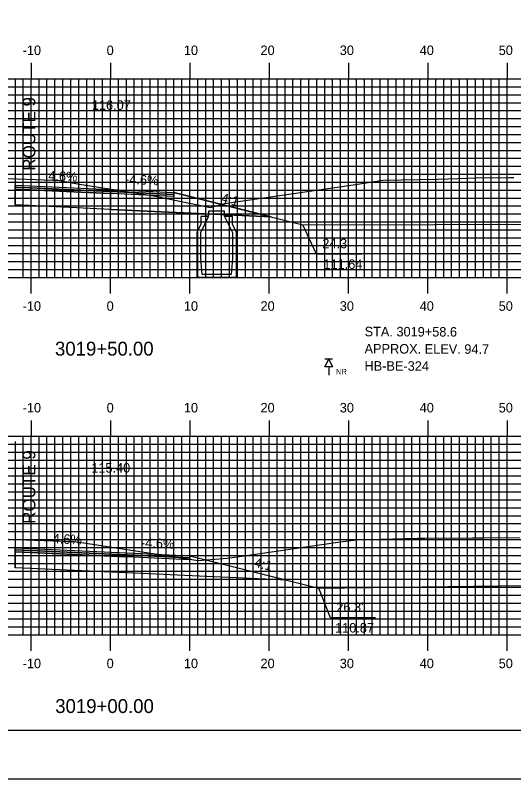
# Model space of a CAD drawing. Extents: x 1685979 to 1686323, y 461260 to 461480.
# Drawn here: x 1686133.3 to 1686196.1, y 461260 to 461356.1 of the extents above; entities that cross this region are included whole.
import ezdxf

# ---------------------------------------------------------------- set-up
doc = ezdxf.new("R2010")
doc.units = 0
for name, color, linetype in [('ANNOTATION', 7, 'Continuous'), ('BORDER', 7, 'Continuous'), ('BORING - NO REFUSAL', 7, 'Continuous'), ('D_Roadway_Centerline_Text', 7, 'Continuous'), ('D_Roadway_Edge_Shoulder', 7, 'Continuous'), ('D_Roadway_Edge_TW', 7, 'Continuous'), ('D_Roadway_Pavement', 7, 'Continuous'), ('D_Roadway_SlopeLines', 7, 'Continuous'), ('D_Roadway_SubGrade', 7, 'Continuous'), ('H_V ANNOTATION', 7, 'Continuous'), ('M_Drainage_CB', 7, 'Continuous'), ('M_Roadway_Centerline', 7, 'Continuous'), ('MAJOR', 7, 'Continuous'), ('MINOR', 7, 'Continuous'), ('PLOT BOUNDARY', 7, 'Continuous'), ('S_Roadway_Centerline', 7, 'Continuous')]:
    doc.layers.add(name, color=color, linetype=linetype)

msp = doc.modelspace()

# ---------------------------------------------------------------- linework, layer by layer
at = {"layer": 'ANNOTATION'}
for points in [[(1686176.917, 461326.019), (1686171.226, 461326.019), (1686169.511, 461329.71)], [(1686178.674, 461280.232), (1686172.982, 461280.232), (1686171.511, 461283.946)]]:
    msp.add_lwpolyline(points, dxfattribs=at)
at = {"layer": 'BORDER'}
msp.add_lwpolyline([(1685995.656, 461266.072), (1686315.656, 461266.072), (1686315.656, 461476.072), (1685995.656, 461476.072)], close=True, dxfattribs=at)
at = {"layer": 'BORING - NO REFUSAL'}
for p, q in [((1686173.235, 461312.772), (1686172.276, 461312.772)), ((1686172.756, 461311.813), (1686172.756, 461310.754))]:
    msp.add_line(p, q, dxfattribs=at)
msp.add_lwpolyline([(1686172.756, 461312.772), (1686173.235, 461311.813), (1686172.276, 461311.813)], close=True, dxfattribs=at)
at = {"layer": 'D_Roadway_Edge_Shoulder'}
msp.add_line((1686133.256, 461288.772), (1686133.256, 461289.022), dxfattribs=at)
for points in [[(1686145.256, 461334.141), (1686153.256, 461333.773), (1686153.256, 461333.523), (1686145.256, 461333.891)], [(1686145.256, 461334.141), (1686153.256, 461333.773), (1686153.256, 461333.523), (1686145.256, 461333.891)], [(1686145.256, 461334.141), (1686153.256, 461333.773), (1686153.256, 461333.523), (1686145.256, 461333.891)], [(1686145.256, 461333.891), (1686153.256, 461333.523), (1686153.256, 461333.273), (1686145.256, 461333.641)], [(1686147.256, 461288.378), (1686155.256, 461288.01), (1686155.256, 461287.76), (1686147.256, 461288.128)], [(1686147.256, 461288.128), (1686155.256, 461287.76), (1686155.256, 461287.51), (1686147.256, 461287.878)]]:
    msp.add_lwpolyline(points, close=True, dxfattribs=at)
at = {"layer": 'D_Roadway_Edge_TW'}
for points in [[(1686133.256, 461334.693), (1686145.256, 461334.141), (1686145.256, 461333.891), (1686133.256, 461334.443)], [(1686133.256, 461334.693), (1686145.256, 461334.141), (1686145.256, 461333.891), (1686133.256, 461334.443)], [(1686133.256, 461334.693), (1686145.256, 461334.141), (1686145.256, 461333.891), (1686133.256, 461334.443)], [(1686133.256, 461289.022), (1686147.256, 461288.378), (1686147.256, 461288.128), (1686133.256, 461288.772)], [(1686133.256, 461289.022), (1686147.256, 461288.378), (1686147.256, 461288.128), (1686133.256, 461288.772)]]:
    msp.add_lwpolyline(points, close=True, dxfattribs=at)
for points in [[(1686133.256, 461334.693), (1686133.256, 461334.443)], [(1686145.256, 461333.891), (1686145.256, 461334.141)], [(1686133.256, 461289.022), (1686133.256, 461288.772)], [(1686147.256, 461288.128), (1686147.256, 461288.378)]]:
    msp.add_lwpolyline(points, dxfattribs=at)
at = {"layer": 'D_Roadway_Pavement'}
msp.add_line((1686133.256, 461288.522), (1686133.256, 461288.772), dxfattribs=at)
for points in [[(1686133.256, 461334.443), (1686145.256, 461333.891), (1686145.256, 461333.641), (1686133.256, 461334.193)], [(1686133.256, 461334.443), (1686145.256, 461333.891), (1686145.256, 461333.641), (1686133.256, 461334.193)], [(1686133.256, 461334.443), (1686145.256, 461333.891), (1686145.256, 461333.641), (1686133.256, 461334.193)], [(1686133.256, 461334.443), (1686145.256, 461333.891), (1686145.256, 461333.641), (1686133.256, 461334.193)], [(1686133.256, 461334.443), (1686145.256, 461333.891), (1686145.256, 461333.641), (1686133.256, 461334.193)], [(1686133.256, 461288.772), (1686147.256, 461288.128), (1686147.256, 461287.878), (1686133.256, 461288.522)]]:
    msp.add_lwpolyline(points, close=True, dxfattribs=at)
for points in [[(1686133.256, 461334.443), (1686133.256, 461334.193)], [(1686145.256, 461333.891), (1686145.256, 461333.641)], [(1686145.256, 461333.891), (1686145.256, 461333.641)], [(1686145.256, 461333.891), (1686145.256, 461333.641)], [(1686145.256, 461333.891), (1686145.256, 461333.641)], [(1686145.256, 461333.891), (1686145.256, 461333.641)], [(1686145.256, 461333.891), (1686145.256, 461333.641)], [(1686145.256, 461333.641), (1686145.256, 461333.891)], [(1686145.256, 461333.891), (1686145.256, 461333.641)], [(1686133.256, 461288.772), (1686133.256, 461288.522)], [(1686147.256, 461288.128), (1686147.256, 461287.878)], [(1686147.256, 461288.128), (1686147.256, 461287.878)], [(1686147.256, 461288.128), (1686147.256, 461287.878)], [(1686147.256, 461288.128), (1686147.256, 461287.878)], [(1686147.256, 461288.128), (1686147.256, 461287.878)], [(1686147.256, 461288.128), (1686147.256, 461287.878)], [(1686147.256, 461287.878), (1686147.256, 461288.128)], [(1686147.256, 461288.128), (1686147.256, 461287.878)]]:
    msp.add_lwpolyline(points, dxfattribs=at)
at = {"layer": 'D_Roadway_SlopeLines'}
for points in [[(1686153.256, 461333.773), (1686169.511, 461329.71)], [(1686153.256, 461333.773), (1686169.511, 461329.71)], [(1686153.256, 461333.773), (1686169.511, 461329.71)], [(1686153.256, 461333.773), (1686169.511, 461329.71)], [(1686169.511, 461329.71), (1686252.38, 461329.925)], [(1686169.511, 461329.71), (1686252.38, 461329.925)], [(1686169.511, 461329.71), (1686252.38, 461329.925)], [(1686169.511, 461329.71), (1686252.38, 461329.925)], [(1686155.256, 461288.01), (1686171.511, 461283.946)], [(1686171.511, 461283.946), (1686249.53, 461284.948)], [(1686171.511, 461283.946), (1686249.53, 461284.948)], [(1686171.511, 461283.946), (1686249.53, 461284.948)], [(1686171.511, 461283.946), (1686249.53, 461284.948)]]:
    msp.add_lwpolyline(points, dxfattribs=at)
at = {"layer": 'D_Roadway_SubGrade'}
for p, q in [((1686133.256, 461348.072), (1686133.256, 461332.193)), ((1686133.256, 461302.4), (1686133.256, 461286.522)), ((1686133.256, 461286.522), (1686133.256, 461288.522))]:
    msp.add_line(p, q, dxfattribs=at)
for points in [[(1686133.256, 461334.193), (1686133.256, 461332.193)], [(1686133.256, 461334.193), (1686133.256, 461332.193)], [(1686133.256, 461288.522), (1686133.256, 461286.522)], [(1686133.256, 461288.522), (1686133.256, 461286.522)]]:
    msp.add_lwpolyline(points, dxfattribs=at)
for points in [[(1686133.256, 461334.193), (1686145.256, 461333.641), (1686145.256, 461331.641), (1686133.256, 461332.193)], [(1686133.256, 461334.193), (1686145.256, 461333.641), (1686145.256, 461331.641), (1686133.256, 461332.193)], [(1686133.256, 461334.193), (1686145.256, 461333.641), (1686145.256, 461331.641), (1686133.256, 461332.193)], [(1686145.256, 461331.641), (1686165.511, 461330.71), (1686153.256, 461333.773), (1686153.256, 461333.523), (1686145.256, 461333.891), (1686145.256, 461333.641)], [(1686145.256, 461333.641), (1686145.256, 461333.891), (1686153.256, 461333.523), (1686153.256, 461333.773), (1686165.511, 461330.71), (1686145.256, 461331.641)], [(1686145.256, 461333.641), (1686145.256, 461333.891), (1686153.256, 461333.523), (1686153.256, 461333.773), (1686165.511, 461330.71), (1686145.256, 461331.641)], [(1686145.256, 461331.641), (1686165.511, 461330.71), (1686153.256, 461333.773), (1686153.256, 461333.523), (1686145.256, 461333.891), (1686145.256, 461333.641)], [(1686133.256, 461288.522), (1686147.256, 461287.878), (1686147.256, 461285.878), (1686133.256, 461286.522)], [(1686133.256, 461288.522), (1686147.256, 461287.878), (1686147.256, 461285.878), (1686133.256, 461286.522)], [(1686133.256, 461288.522), (1686147.256, 461287.878), (1686147.256, 461285.878), (1686133.256, 461286.522)], [(1686147.256, 461287.878), (1686147.256, 461288.128), (1686155.256, 461287.76), (1686155.256, 461288.01), (1686167.511, 461284.946), (1686147.256, 461285.878)]]:
    msp.add_lwpolyline(points, close=True, dxfattribs=at)
at = {"layer": 'M_Drainage_CB'}
for p, q in [((1686157.617, 461330.751), (1686156.633, 461330.751)), ((1686156.633, 461330.751), (1686156.633, 461329.766)), ((1686156.633, 461328.749), (1686157.617, 461330.751)), ((1686160.636, 461330.751), (1686159.619, 461330.751)), ((1686159.619, 461330.751), (1686160.636, 461328.749)), ((1686160.636, 461329.766), (1686160.636, 461330.751)), ((1686156.633, 461329.766), (1686156.141, 461328.749)), ((1686161.128, 461328.749), (1686160.636, 461329.766)), ((1686156.141, 461328.749), (1686156.141, 461323.106)), ((1686156.633, 461325.436), (1686156.633, 461328.749)), ((1686160.636, 461328.749), (1686160.636, 461325.436)), ((1686161.128, 461323.106), (1686161.128, 461328.749)), ((1686156.797, 461323.434), (1686156.633, 461325.436)), ((1686160.636, 461325.436), (1686160.472, 461323.434)), ((1686156.141, 461323.106), (1686161.128, 461323.106)), ((1686160.472, 461323.434), (1686156.797, 461323.434))]:
    msp.add_line(p, q, dxfattribs=at)
msp.add_lwpolyline([(1686160.111, 461330.792), (1686159.619, 461330.792), (1686159.619, 461331.416), (1686157.617, 461331.416), (1686157.617, 461330.792), (1686157.125, 461330.792)], dxfattribs=at)
at = {"layer": 'MAJOR'}
for p, q in [((1686135.256, 461350.076), (1686135.256, 461348.072)), ((1686145.256, 461350.076), (1686145.256, 461348.072)), ((1686155.256, 461350.076), (1686155.256, 461348.072)), ((1686165.256, 461350.076), (1686165.256, 461348.072)), ((1686175.256, 461350.076), (1686175.256, 461348.072)), ((1686185.256, 461350.076), (1686185.256, 461348.072)), ((1686195.256, 461350.076), (1686195.256, 461348.072)), ((1686005.256, 461348.072), (1686285.256, 461348.072)), ((1686005.256, 461348.072), (1686285.256, 461348.072)), ((1686135.256, 461323.072), (1686135.256, 461348.072)), ((1686145.256, 461323.072), (1686145.256, 461348.072)), ((1686155.256, 461323.072), (1686155.256, 461348.072)), ((1686165.256, 461323.072), (1686165.256, 461348.072)), ((1686175.256, 461323.072), (1686175.256, 461348.072)), ((1686185.256, 461323.072), (1686185.256, 461348.072)), ((1686195.256, 461323.072), (1686195.256, 461348.072)), ((1686005.256, 461343.072), (1686285.256, 461343.072)), ((1686005.256, 461338.072), (1686285.256, 461338.072)), ((1686005.256, 461333.072), (1686285.256, 461333.072)), ((1686005.256, 461328.072), (1686285.256, 461328.072)), ((1686005.256, 461323.072), (1686285.256, 461323.072)), ((1686005.256, 461323.072), (1686285.256, 461323.072)), ((1686135.256, 461321.068), (1686135.256, 461323.072)), ((1686145.256, 461321.068), (1686145.256, 461323.072)), ((1686155.256, 461321.068), (1686155.256, 461323.072)), ((1686165.256, 461321.068), (1686165.256, 461323.072)), ((1686175.256, 461321.068), (1686175.256, 461323.072)), ((1686185.256, 461321.068), (1686185.256, 461323.072)), ((1686195.256, 461321.068), (1686195.256, 461323.072)), ((1686135.256, 461305.076), (1686135.256, 461303.072)), ((1686145.256, 461305.076), (1686145.256, 461303.072)), ((1686155.256, 461305.076), (1686155.256, 461303.072)), ((1686165.256, 461305.076), (1686165.256, 461303.072)), ((1686175.256, 461305.076), (1686175.256, 461303.072)), ((1686185.256, 461305.076), (1686185.256, 461303.072)), ((1686195.256, 461305.076), (1686195.256, 461303.072)), ((1686005.256, 461303.072), (1686285.256, 461303.072)), ((1686005.256, 461303.072), (1686285.256, 461303.072)), ((1686135.256, 461278.072), (1686135.256, 461303.072)), ((1686145.256, 461278.072), (1686145.256, 461303.072)), ((1686155.256, 461278.072), (1686155.256, 461303.072)), ((1686165.256, 461278.072), (1686165.256, 461303.072)), ((1686175.256, 461278.072), (1686175.256, 461303.072)), ((1686185.256, 461278.072), (1686185.256, 461303.072)), ((1686195.256, 461278.072), (1686195.256, 461303.072)), ((1686005.256, 461298.072), (1686285.256, 461298.072)), ((1686005.256, 461293.072), (1686285.256, 461293.072)), ((1686005.256, 461288.072), (1686285.256, 461288.072)), ((1686005.256, 461283.072), (1686285.256, 461283.072)), ((1686005.256, 461278.072), (1686285.256, 461278.072)), ((1686005.256, 461278.072), (1686285.256, 461278.072)), ((1686135.256, 461276.068), (1686135.256, 461278.072)), ((1686145.256, 461276.068), (1686145.256, 461278.072)), ((1686155.256, 461276.068), (1686155.256, 461278.072)), ((1686165.256, 461276.068), (1686165.256, 461278.072)), ((1686175.256, 461276.068), (1686175.256, 461278.072)), ((1686185.256, 461276.068), (1686185.256, 461278.072)), ((1686195.256, 461276.068), (1686195.256, 461278.072))]:
    msp.add_line(p, q, dxfattribs=at)
at = {"layer": 'MINOR'}
for p, q in [((1686134.256, 461323.072), (1686134.256, 461348.072)), ((1686136.256, 461323.072), (1686136.256, 461348.072)), ((1686137.256, 461323.072), (1686137.256, 461348.072)), ((1686138.256, 461323.072), (1686138.256, 461348.072)), ((1686139.256, 461323.072), (1686139.256, 461348.072)), ((1686140.256, 461323.072), (1686140.256, 461348.072)), ((1686141.256, 461323.072), (1686141.256, 461348.072)), ((1686142.256, 461323.072), (1686142.256, 461348.072)), ((1686143.256, 461323.072), (1686143.256, 461348.072)), ((1686144.256, 461323.072), (1686144.256, 461348.072)), ((1686146.256, 461323.072), (1686146.256, 461348.072)), ((1686147.256, 461323.072), (1686147.256, 461348.072)), ((1686148.256, 461323.072), (1686148.256, 461348.072)), ((1686149.256, 461323.072), (1686149.256, 461348.072)), ((1686150.256, 461323.072), (1686150.256, 461348.072)), ((1686151.256, 461323.072), (1686151.256, 461348.072)), ((1686152.256, 461323.072), (1686152.256, 461348.072)), ((1686153.256, 461323.072), (1686153.256, 461348.072)), ((1686154.256, 461323.072), (1686154.256, 461348.072)), ((1686156.256, 461323.072), (1686156.256, 461348.072)), ((1686157.256, 461323.072), (1686157.256, 461348.072)), ((1686158.256, 461323.072), (1686158.256, 461348.072)), ((1686159.256, 461323.072), (1686159.256, 461348.072)), ((1686160.256, 461323.072), (1686160.256, 461348.072)), ((1686161.256, 461323.072), (1686161.256, 461348.072)), ((1686162.256, 461323.072), (1686162.256, 461348.072)), ((1686163.256, 461323.072), (1686163.256, 461348.072)), ((1686164.256, 461323.072), (1686164.256, 461348.072)), ((1686166.256, 461323.072), (1686166.256, 461348.072)), ((1686167.256, 461323.072), (1686167.256, 461348.072)), ((1686168.256, 461323.072), (1686168.256, 461348.072)), ((1686169.256, 461323.072), (1686169.256, 461348.072)), ((1686170.256, 461323.072), (1686170.256, 461348.072)), ((1686171.256, 461323.072), (1686171.256, 461348.072)), ((1686172.256, 461323.072), (1686172.256, 461348.072)), ((1686173.256, 461323.072), (1686173.256, 461348.072)), ((1686174.256, 461323.072), (1686174.256, 461348.072)), ((1686176.256, 461323.072), (1686176.256, 461348.072)), ((1686177.256, 461323.072), (1686177.256, 461348.072)), ((1686178.256, 461323.072), (1686178.256, 461348.072)), ((1686179.256, 461323.072), (1686179.256, 461348.072)), ((1686180.256, 461323.072), (1686180.256, 461348.072)), ((1686181.256, 461323.072), (1686181.256, 461348.072)), ((1686182.256, 461323.072), (1686182.256, 461348.072)), ((1686183.256, 461323.072), (1686183.256, 461348.072)), ((1686184.256, 461323.072), (1686184.256, 461348.072)), ((1686186.256, 461323.072), (1686186.256, 461348.072)), ((1686187.256, 461323.072), (1686187.256, 461348.072)), ((1686188.256, 461323.072), (1686188.256, 461348.072)), ((1686189.256, 461323.072), (1686189.256, 461348.072)), ((1686190.256, 461323.072), (1686190.256, 461348.072)), ((1686191.256, 461323.072), (1686191.256, 461348.072)), ((1686192.256, 461323.072), (1686192.256, 461348.072)), ((1686193.256, 461323.072), (1686193.256, 461348.072)), ((1686194.256, 461323.072), (1686194.256, 461348.072)), ((1686005.256, 461347.072), (1686285.256, 461347.072)), ((1686005.256, 461346.072), (1686285.256, 461346.072)), ((1686005.256, 461345.072), (1686285.256, 461345.072)), ((1686005.256, 461344.072), (1686285.256, 461344.072)), ((1686005.256, 461342.072), (1686285.256, 461342.072)), ((1686005.256, 461341.072), (1686285.256, 461341.072)), ((1686005.256, 461340.072), (1686285.256, 461340.072)), ((1686005.256, 461339.072), (1686285.256, 461339.072)), ((1686005.256, 461337.072), (1686285.256, 461337.072)), ((1686005.256, 461336.072), (1686285.256, 461336.072)), ((1686005.256, 461335.072), (1686285.256, 461335.072)), ((1686005.256, 461334.072), (1686285.256, 461334.072)), ((1686005.256, 461332.072), (1686285.256, 461332.072)), ((1686005.256, 461331.072), (1686285.256, 461331.072)), ((1686005.256, 461330.072), (1686285.256, 461330.072)), ((1686005.256, 461329.072), (1686285.256, 461329.072)), ((1686005.256, 461327.072), (1686285.256, 461327.072)), ((1686005.256, 461326.072), (1686285.256, 461326.072)), ((1686005.256, 461325.072), (1686285.256, 461325.072)), ((1686005.256, 461324.072), (1686285.256, 461324.072)), ((1686134.256, 461278.072), (1686134.256, 461303.072)), ((1686136.256, 461278.072), (1686136.256, 461303.072)), ((1686137.256, 461278.072), (1686137.256, 461303.072)), ((1686138.256, 461278.072), (1686138.256, 461303.072)), ((1686139.256, 461278.072), (1686139.256, 461303.072)), ((1686140.256, 461278.072), (1686140.256, 461303.072)), ((1686141.256, 461278.072), (1686141.256, 461303.072)), ((1686142.256, 461278.072), (1686142.256, 461303.072)), ((1686143.256, 461278.072), (1686143.256, 461303.072)), ((1686144.256, 461278.072), (1686144.256, 461303.072)), ((1686146.256, 461278.072), (1686146.256, 461303.072)), ((1686147.256, 461278.072), (1686147.256, 461303.072)), ((1686148.256, 461278.072), (1686148.256, 461303.072)), ((1686149.256, 461278.072), (1686149.256, 461303.072)), ((1686150.256, 461278.072), (1686150.256, 461303.072)), ((1686151.256, 461278.072), (1686151.256, 461303.072)), ((1686152.256, 461278.072), (1686152.256, 461303.072)), ((1686153.256, 461278.072), (1686153.256, 461303.072)), ((1686154.256, 461278.072), (1686154.256, 461303.072)), ((1686156.256, 461278.072), (1686156.256, 461303.072)), ((1686157.256, 461278.072), (1686157.256, 461303.072)), ((1686158.256, 461278.072), (1686158.256, 461303.072)), ((1686159.256, 461278.072), (1686159.256, 461303.072)), ((1686160.256, 461278.072), (1686160.256, 461303.072)), ((1686161.256, 461278.072), (1686161.256, 461303.072)), ((1686162.256, 461278.072), (1686162.256, 461303.072)), ((1686163.256, 461278.072), (1686163.256, 461303.072)), ((1686164.256, 461278.072), (1686164.256, 461303.072)), ((1686166.256, 461278.072), (1686166.256, 461303.072)), ((1686167.256, 461278.072), (1686167.256, 461303.072)), ((1686168.256, 461278.072), (1686168.256, 461303.072)), ((1686169.256, 461278.072), (1686169.256, 461303.072)), ((1686170.256, 461278.072), (1686170.256, 461303.072)), ((1686171.256, 461278.072), (1686171.256, 461303.072)), ((1686172.256, 461278.072), (1686172.256, 461303.072)), ((1686173.256, 461278.072), (1686173.256, 461303.072)), ((1686174.256, 461278.072), (1686174.256, 461303.072)), ((1686176.256, 461278.072), (1686176.256, 461303.072)), ((1686177.256, 461278.072), (1686177.256, 461303.072)), ((1686178.256, 461278.072), (1686178.256, 461303.072)), ((1686179.256, 461278.072), (1686179.256, 461303.072)), ((1686180.256, 461278.072), (1686180.256, 461303.072)), ((1686181.256, 461278.072), (1686181.256, 461303.072)), ((1686182.256, 461278.072), (1686182.256, 461303.072)), ((1686183.256, 461278.072), (1686183.256, 461303.072)), ((1686184.256, 461278.072), (1686184.256, 461303.072)), ((1686186.256, 461278.072), (1686186.256, 461303.072)), ((1686187.256, 461278.072), (1686187.256, 461303.072)), ((1686188.256, 461278.072), (1686188.256, 461303.072)), ((1686189.256, 461278.072), (1686189.256, 461303.072)), ((1686190.256, 461278.072), (1686190.256, 461303.072)), ((1686191.256, 461278.072), (1686191.256, 461303.072)), ((1686192.256, 461278.072), (1686192.256, 461303.072)), ((1686193.256, 461278.072), (1686193.256, 461303.072)), ((1686194.256, 461278.072), (1686194.256, 461303.072)), ((1686005.256, 461302.072), (1686285.256, 461302.072)), ((1686005.256, 461301.072), (1686285.256, 461301.072)), ((1686005.256, 461300.072), (1686285.256, 461300.072)), ((1686005.256, 461299.072), (1686285.256, 461299.072)), ((1686005.256, 461297.072), (1686285.256, 461297.072)), ((1686005.256, 461296.072), (1686285.256, 461296.072)), ((1686005.256, 461295.072), (1686285.256, 461295.072)), ((1686005.256, 461294.072), (1686285.256, 461294.072)), ((1686005.256, 461292.072), (1686285.256, 461292.072)), ((1686005.256, 461291.072), (1686285.256, 461291.072)), ((1686005.256, 461290.072), (1686285.256, 461290.072)), ((1686005.256, 461289.072), (1686285.256, 461289.072)), ((1686005.256, 461287.072), (1686285.256, 461287.072)), ((1686005.256, 461286.072), (1686285.256, 461286.072)), ((1686005.256, 461285.072), (1686285.256, 461285.072)), ((1686005.256, 461284.072), (1686285.256, 461284.072)), ((1686005.256, 461282.072), (1686285.256, 461282.072)), ((1686005.256, 461281.072), (1686285.256, 461281.072)), ((1686005.256, 461280.072), (1686285.256, 461280.072)), ((1686005.256, 461279.072), (1686285.256, 461279.072))]:
    msp.add_line(p, q, dxfattribs=at)
at = {"layer": 'PLOT BOUNDARY'}
msp.add_lwpolyline([(1685979.469, 461259.954), (1686319.469, 461259.954), (1686319.469, 461479.954), (1685979.469, 461479.954)], close=True, dxfattribs=at)
at = {"layer": 'S_Roadway_Centerline'}
for points in [[(1686127.868, 461335.688), (1686137.986, 461335.334), (1686138.631, 461335.302), (1686139.051, 461335.246), (1686141.611, 461334.774), (1686149.135, 461333.6), (1686150.93, 461333.322), (1686157.853, 461331.891), (1686159.62, 461332.386), (1686176.141, 461334.791), (1686178.818, 461335.175), (1686179.593, 461335.322), (1686186.566, 461335.461), (1686190.251, 461335.585), (1686191.202, 461335.603), (1686195.53, 461335.674), (1686196.087, 461335.655)], [(1686127.982, 461290.301), (1686135.668, 461290.009), (1686139.277, 461289.872), (1686140.352, 461289.837), (1686140.619, 461289.822), (1686141.901, 461289.653), (1686155.77, 461287.531), (1686156.319, 461287.423), (1686159.973, 461287.705), (1686161.826, 461287.974), (1686173.89, 461289.76), (1686176.225, 461290.037), (1686183.949, 461290.229), (1686184.876, 461290.247), (1686190.828, 461290.28), (1686192.151, 461290.287), (1686193.611, 461290.316), (1686196.862, 461290.273)]]:
    msp.add_lwpolyline(points, dxfattribs=at)

# ---------------------------------------------------------------- texts
at = {"layer": 'ANNOTATION'}
for s, height, rotation, p in [('ROUTE 9', 1.6, 90, (1686135.787, 461336.516)), ('4.6%', 1.2, 357.36625, (1686137.402, 461335.305)), ('-4.6%', 1.2, 357.36625, (1686147.081, 461334.86)), ('4:1', 1.2, 345.96376, (1686159.106, 461332.551)), ('ROUTE 9', 1.6, 90, (1686135.787, 461292.043)), ('4.6%', 1.2, 357.36622, (1686137.963, 461289.607)), ('-4.6%', 1.2, 357.36625, (1686149.081, 461289.096)), ('4:1', 1.2, 345.96376, (1686163.3, 461286.653))]:
    msp.add_text(s, height=height, rotation=rotation, dxfattribs=at).set_placement(p)
for s, p in [("24.3' ", (1686171.96, 461326.745)), ('111.64', (1686172.095, 461324.145)), ("26.3' ", (1686173.717, 461280.958)), ('110.87', (1686173.562, 461278.358))]:
    msp.add_text(s, height=1.2, dxfattribs=at).set_placement(p)
at = {"layer": 'BORING - NO REFUSAL'}
for s, p in [('STA. 3019+58.6', (1686177.285, 461315.659)), ('APPROX. ELEV. 94.7', (1686177.278, 461313.499)), ('HB-BE-324', (1686177.271, 461311.339))]:
    msp.add_text(s, height=1.2, rotation=359.81416, dxfattribs=at).set_placement(p)
msp.add_text('NR', height=0.6998, dxfattribs=at).set_placement((1686173.688, 461310.857))
at = {"layer": 'D_Roadway_Centerline_Text'}
for s, p in [('116.07', (1686142.912, 461344.171)), ('115.40', (1686142.837, 461298.5))]:
    msp.add_text(s, height=1.2, dxfattribs=at).set_placement(p)
at = {"layer": 'H_V ANNOTATION'}
for s, height, p in [('-10', 1.2, (1686134.185, 461351.072)), ('0', 1.2, (1686144.774, 461351.072)), ('10', 1.2, (1686154.506, 461351.072)), ('20', 1.2, (1686164.164, 461351.072)), ('30', 1.2, (1686174.153, 461351.072)), ('40', 1.2, (1686184.228, 461351.072)), ('50', 1.2, (1686194.185, 461351.072)), ('-10', 1.2, (1686134.185, 461318.872)), ('0', 1.2, (1686144.774, 461318.872)), ('10', 1.2, (1686154.506, 461318.872)), ('20', 1.2, (1686164.164, 461318.872)), ('30', 1.2, (1686174.153, 461318.872)), ('40', 1.2, (1686184.228, 461318.872)), ('50', 1.2, (1686194.185, 461318.872)), ('3019+50.00', 1.75, (1686138.264, 461313.228)), ('-10', 1.2, (1686134.185, 461306.072)), ('0', 1.2, (1686144.774, 461306.072)), ('10', 1.2, (1686154.506, 461306.072)), ('20', 1.2, (1686164.164, 461306.072)), ('30', 1.2, (1686174.153, 461306.072)), ('40', 1.2, (1686184.228, 461306.072)), ('50', 1.2, (1686194.185, 461306.072)), ('-10', 1.2, (1686134.185, 461273.872)), ('0', 1.2, (1686144.774, 461273.872)), ('10', 1.2, (1686154.506, 461273.872)), ('20', 1.2, (1686164.164, 461273.872)), ('30', 1.2, (1686174.153, 461273.872)), ('40', 1.2, (1686184.228, 461273.872)), ('50', 1.2, (1686194.185, 461273.872)), ('3019+00.00', 1.75, (1686138.295, 461268.228))]:
    msp.add_text(s, height=height, dxfattribs=at).set_placement(p)
at = {"layer": 'M_Roadway_Centerline'}
for s, p in [('C', (1686195.525, 461335.674)), ('L', (1686195.53, 461335.666)), ('C', (1686192.146, 461290.287)), ('L', (1686192.151, 461290.28))]:
    msp.add_text(s, height=0.0146, dxfattribs=at).set_placement(p)

doc.saveas('drawing.dxf')
